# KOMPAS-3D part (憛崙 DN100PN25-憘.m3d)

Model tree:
1. Объединить компоненты:1  (labels: СЕНС DN100PN25)
2. Эскиз:1
3. Операция выдавливания:1
     Расстояние 1 = 14
4. Фаска:1
     Угол = 45; Длина 1 = 2; Длина 2 = 2

Referenced files in D:\Савин\!СЕНСОР\3D для заказчика\!Новый перечень\СЕНС\1. СЕНС\DN100\: СЕНС DN100PN25.a3d
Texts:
  СЕНС DN100PN25-СВ
  ООО НПП Сенсор
  СЕНС DN100PN25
